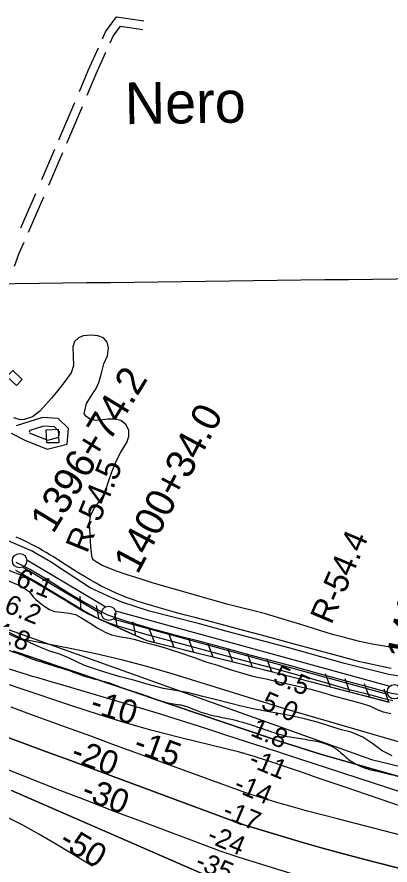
# Model space of a CAD drawing. Extents: x 3734862 to 3772949, y 391520 to 417239.
# Drawn here: x 3742804 to 3744100, y 406999 to 409950 of the extents above; entities that cross this region are included whole.
import ezdxf

# ---------------------------------------------------------------- set-up
doc = ezdxf.new("R2010")
doc.units = 0
for name, color, linetype in [('V-BLDG-OTLN', 7, 'Continuous'), ('V-FLOD-BASE', 7, 'Continuous'), ('V-GRID-MAJR', 7, 'Continuous'), ('V-LEVE-TOET', 7, 'Continuous'), ('V-RIVR-EDGE', 7, 'Continuous'), ('V-RIVR-RANG', 7, 'Continuous'), ('V-RIVR-RANG-IDEN', 7, 'Continuous'), ('V-ROAD-CNTR', 7, 'Continuous'), ('V-RRAP-FSHR', 7, 'Continuous'), ('V-SITE-VEGE', 7, 'Continuous'), ('V-SURV-IDEN', 7, 'Continuous'), ('V-SURV-LINE', 7, 'Continuous'), ('V-TOPO-DPTH', 7, 'Continuous'), ('V-TOPO-GNAM-IDEN', 7, 'Continuous'), ('V-TOPO-MAJR', 7, 'Continuous'), ('V-TOPO-MAJR-IDEN', 7, 'Continuous'), ('V-TOPO-MINR', 7, 'Continuous'), ('V-TOPO-MINR-IDEN', 7, 'Continuous'), ('V-TOPO-WATR', 7, 'Continuous')]:
    doc.layers.add(name, color=color, linetype=linetype)

msp = doc.modelspace()

# ---------------------------------------------------------------- linework, layer by layer
at = {"layer": 'V-BLDG-OTLN'}
for points in [[(3742788.9, 408720.5), (3742822, 408688.6), (3742801.7, 408667.5), (3742768.2, 408699.8)], [(3742907.2, 408468.1), (3742904.8, 408513.3), (3742946.3, 408515.6), (3742948.7, 408468.9)]]:
    msp.add_lwpolyline(points, close=True, dxfattribs=at)
at = {"layer": 'V-FLOD-BASE'}
msp.add_lwpolyline([(3742799.2, 408053.1), (3742853, 408026.1), (3742909.9, 407993.3), (3742979.3, 407948.5), (3743033, 407916.4), (3743093.5, 407882.5), (3743118.4, 407870.1), (3743180.9, 407848.5), (3743270.2, 407822.1), (3743352.5, 407800.2), (3743431.3, 407780.8), (3743537.5, 407751.6), (3743621.3, 407728.9), (3743741.1, 407696.7), (3743844, 407668.5), (3743951.5, 407639.3), (3744046.6, 407613.7), (3744099.5, 407598.1), (3744126.7, 407594.1)], dxfattribs=at)
at = {"layer": 'V-GRID-MAJR'}
msp.add_spline([(3738908.6, 408973.5), (3741556.3, 409006.9), (3746851.6, 409074.3), (3752147, 409142.5), (3757442.4, 409211.4), (3762737.7, 409281.1), (3768033.1, 409351.6), (3770680.7, 409387.1)], degree=3, dxfattribs=at)
at = {"layer": 'V-LEVE-TOET'}
for points in [[(3744215.9, 407644.2), (3744095.8, 407661.7), (3743941.3, 407700.9), (3743748.5, 407754.7), (3743534.5, 407811.6), (3743437.6, 407838.2), (3743263.6, 407883.2), (3743167.7, 407913.4), (3743132.9, 407929.5), (3743057.5, 407964.3), (3742970.5, 408021.1), (3742919.8, 408054.2), (3742853.7, 408092.6), (3742773.2, 408127.8)], [(3742798.5, 408024.9), (3742869.2, 407985.5), (3742995.7, 407909.4), (3743042.3, 407880.5), (3743097.7, 407851.4), (3743145.9, 407833.8), (3743246.4, 407803.5), (3743394.2, 407764.3), (3743526.5, 407727.8), (3743703, 407681.8), (3743863, 407637.4), (3743952.8, 407610.8), (3744015.4, 407596.7), (3744070.8, 407581.5), (3744109.3, 407572.1)]]:
    msp.add_lwpolyline(points, dxfattribs=at)
at = {"layer": 'V-RIVR-EDGE'}
msp.add_spline([(3740900.6, 408488.8), (3740941.7, 408478.3), (3740985.5, 408468.7), (3741012.2, 408464.1), (3741026.2, 408456.3), (3741048.3, 408440), (3741059.6, 408430.9), (3741079.5, 408419.1), (3741115.6, 408401), (3741134.5, 408387.8), (3741159.8, 408374.2), (3741187.8, 408359.6), (3741219.5, 408345.5), (3741247.5, 408335.1), (3741273.7, 408327.8), (3741324.3, 408308.2), (3741367.6, 408293.6), (3741397.4, 408282.7), (3741437.2, 408266.3), (3741481, 408247.7), (3741515.8, 408234), (3741546.1, 408221.7), (3741577.7, 408210.8), (3741596.2, 408209.4), (3741611.6, 408211.2), (3741627.9, 408209.8), (3741654.5, 408199.8), (3741683.9, 408190.2), (3741714.6, 408176.6), (3741739.9, 408164.7), (3741769.2, 408150.2), (3741796.8, 408143.4), (3741811.3, 408142.9), (3741833, 408141.9), (3741852, 408139.2), (3741871.9, 408137.3), (3741889, 408130.9), (3741941.9, 408104.1), (3741978.4, 408082.3), (3742006.4, 408070), (3742031.3, 408063.2), (3742056.1, 408055.9), (3742093.6, 408044.1), (3742137, 408031.3), (3742175.9, 408019), (3742202.5, 408008.5), (3742263, 407982.6), (3742313.2, 407957.1), (3742385.9, 407923.1), (3742430.1, 407901.7), (3742465.8, 407884.9), (3742513.7, 407864.4), (3742632, 407810.8), (3742679, 407791.7), (3742732.3, 407768), (3742777.5, 407745.7), (3742821.3, 407730.3), (3742862.4, 407714.3), (3742898.5, 407703.4), (3742934.7, 407691.5), (3742978.1, 407678.3), (3743028.2, 407660.1), (3743075.6, 407646), (3743127.6, 407631.8), (3743163.7, 407617.7), (3743235.1, 407594.5), (3743327.3, 407564), (3743354.9, 407558.9), (3743372.9, 407556.2), (3743388.8, 407552.5), (3743422.2, 407539.3), (3743470.5, 407523.4), (3743543.3, 407507.4), (3743582.6, 407497.8), (3743628.7, 407483.2), (3743673, 407468.2), (3743714.5, 407454.9), (3743752.5, 407444.9), (3743782.3, 407441.2), (3743812.6, 407435.3), (3743846, 407429.8), (3743877.2, 407420.6), (3743909.3, 407405.6), (3743934.1, 407386.1), (3743951.2, 407370.7), (3743984.2, 407349.4), (3744023, 407333.5), (3744066, 407323), (3744101.7, 407314.7), (3744133.8, 407306.5), (3744170.4, 407296.9), (3744207.4, 407286.9), (3744225, 407281.9), (3744312.2, 407256.8), (3744386.8, 407239.4), (3744416.2, 407234.4), (3744442.4, 407231.1), (3744469.5, 407231.5), (3744498.9, 407232.4), (3744525.6, 407231.4), (3744550, 407229.1), (3744580.7, 407220.9), (3744636.8, 407206.2), (3744682.4, 407187.6), (3744706.3, 407179.4), (3744748.4, 407171.6), (3744781.8, 407164.7), (3744803.1, 407162.9), (3744835.6, 407151), (3744852.3, 407141.5), (3744920.9, 407114.2), (3744972.9, 407087.9), (3745004.9, 407074.7), (3745034.3, 407066.9), (3745066.9, 407060), (3745090.8, 407058.2), (3745113.4, 407050.9), (3745145.9, 407034.1), (3745173, 407020.9), (3745183.4, 407002.8), (3745197.8, 406988.3), (3745221.3, 406974.6), (3745251.1, 406965.5), (3745295.8, 406956.4), (3745336.1, 406954.5), (3745373.6, 406952.6), (3745408, 406947.5), (3745450, 406939.3), (3745483, 406933.3), (3745526.4, 406935), (3745594.2, 406936.6), (3745631.8, 406936.6), (3745647.6, 406941), (3745660.7, 406948.7), (3745673.8, 406949.1), (3745691, 406946.8), (3745714.5, 406937.7), (3745744.8, 406922.3), (3745760.5, 406906.8), (3745773.2, 406890.1), (3745781.3, 406886), (3745798, 406881), (3745819.7, 406879.6), (3745874.4, 406866.3), (3745905.1, 406854.5), (3745930.8, 406838.6), (3745969.2, 406814.1), (3745999, 406799.1), (3746028.8, 406787.3), (3746069.5, 406776.8), (3746110.2, 406766.7), (3746145, 406757.1), (3746173.9, 406747.1), (3746214.5, 406737.1), (3746271.5, 406722.5), (3746336.1, 406708.3), (3746374.5, 406695.1), (3746423.3, 406678.7), (3746514.1, 406654.9), (3746563.4, 406641.3), (3746619.4, 406622.1), (3746668.6, 406606.2), (3746708.4, 406594.3), (3746774.4, 406574.3), (3746826.3, 406564.6), (3746866.1, 406562.7), (3746897.3, 406558.1), (3746931.7, 406550.4)], degree=3, dxfattribs=at)
at = {"layer": 'V-ROAD-CNTR'}
for points in [[(3743100.7, 409874.1), (3743111.7, 409898.8), (3743149.6, 409950.4), (3743244.8, 409936.4)], [(3743127.4, 409860.3), (3743137.8, 409883.7), (3743163.1, 409918.1), (3743240.5, 409906.7)], [(3743020.5, 409690.6), (3743051.5, 409764), (3743086.7, 409842.7)], [(3743047.9, 409678.3), (3743079.1, 409752), (3743112.8, 409827.7)], [(3742949.2, 409522.5), (3742966.5, 409563.1), (3743004.4, 409652.5)], [(3742976.7, 409510.7), (3742994.1, 409551.3), (3743031.3, 409639)], [(3742890.1, 409384.6), (3742935.3, 409490)], [(3742914.3, 409365.1), (3742962.8, 409478.2)], [(3742817.4, 409216.5), (3742869.2, 409335.9)], [(3742843.7, 409201.8), (3742896.7, 409323.9)], [(3742795.3, 409083.6), (3742811.7, 409128.1), (3742828.3, 409166.3)], [(3742783.6, 408502.5), (3742830.8, 408477.3), (3742908.8, 408446), (3742977.4, 408464.2), (3742982.3, 408518.8), (3742947, 408553), (3742892.4, 408556.7), (3742800.4, 408527.3)], [(3742845.7, 408503.6), (3742910.7, 408477.5), (3742949.4, 408487.8), (3742951.2, 408507.2), (3742934, 408523.8), (3742896.1, 408526.4), (3742848.6, 408511.2), (3742846.1, 408505.2)], [(3744104.1, 407683.3), (3744082.2, 407687.5), (3744060.4, 407691.9), (3744038.6, 407696.6), (3744016.8, 407701.5), (3743995.1, 407706.6), (3743918.1, 407727.7), (3743841, 407748.4), (3743763.8, 407768.8), (3743670.8, 407793.9), (3743577.7, 407819), (3743484.7, 407844), (3743452.9, 407852), (3743421.1, 407860.3), (3743389.4, 407868.7), (3743357.7, 407877.3), (3743326.1, 407886.2), (3743294.6, 407895.3), (3743263.1, 407904.6), (3743249.8, 407908.4), (3743236.7, 407912.5), (3743223.5, 407916.8), (3743210.5, 407921.2), (3743197.5, 407925.9), (3743184.6, 407930.7), (3743171.7, 407935.8), (3743159, 407941), (3743146.3, 407946.4), (3743133.7, 407952.1), (3743121.2, 407957.9), (3743108.8, 407963.9), (3743096.5, 407970.1), (3743076.8, 407981), (3743057.4, 407992.2), (3743038, 408003.5), (3743018.7, 408015.1), (3742999.5, 408026.8), (3742980.5, 408038.8), (3742961.6, 408050.9), (3742942.8, 408063.2), (3742930.5, 408071.2), (3742918, 408079), (3742905.4, 408086.7), (3742892.7, 408094.1), (3742879.9, 408101.3), (3742867, 408108.3), (3742854, 408115.2), (3742840.8, 408121.8), (3742827.6, 408128.2), (3742814.3, 408134.4), (3742800.9, 408140.4)]]:
    msp.add_lwpolyline(points, dxfattribs=at)
at = {"layer": 'V-RRAP-FSHR'}
for p, q in [((3743026.8, 407886.4), (3743023.4, 407935.1)), ((3743089.2, 407854.8), (3743080.2, 407902.8)), ((3743153, 407826), (3743143.9, 407874)), ((3743216.7, 407797.1), (3743207.7, 407845.1)), ((3743282.1, 407772.9), (3743264.6, 407818.5)), ((3743350.1, 407756.1), (3743332.5, 407801.6)), ((3743418, 407739.2), (3743400.5, 407784.8)), ((3743485.9, 407722.3), (3743468.4, 407767.9)), ((3743553.9, 407705.4), (3743536.3, 407751)), ((3743621.7, 407688.3), (3743604.5, 407734)), ((3743689.6, 407671), (3743672.3, 407716.7)), ((3743892.9, 407618.7), (3743875.9, 407664.4)), ((3743960.7, 407601.1), (3743943.6, 407646.8)), ((3744028.4, 407583.5), (3744011.4, 407629.2)), ((3744096.2, 407565.8), (3744079.1, 407611.6))]:
    msp.add_line(p, q, dxfattribs=at)
for points in [[(3744098.3, 407565.3), (3743827.4, 407635.7), (3743592.3, 407695.9), (3743255.4, 407779.6), (3743049.2, 407873), (3742833, 408002.6), (3742229.9, 408229.5), (3742052.9, 408246.4), (3741887.5, 408295.6), (3741885.3, 408291.4)], [(3742367.7, 407964), (3744035.9, 407366.8), (3745769.8, 406946.2), (3746228.8, 406810.1), (3747274.2, 406525.6), (3748829.6, 406241.1), (3749734.8, 405944.3), (3750537.9, 405672.1), (3750818.4, 405622.6)], [(3743026.8, 407886.4), (3742980.5, 407914.1)], [(3743089.2, 407854.8), (3743049.2, 407873), (3743026.8, 407886.4)], [(3743153, 407826), (3743089.2, 407854.8)], [(3743216.7, 407797.1), (3743153, 407826)], [(3743282.1, 407772.9), (3743255.4, 407779.6), (3743216.7, 407797.1)], [(3743350.1, 407756.1), (3743282.1, 407772.9)], [(3743418, 407739.2), (3743350.1, 407756.1)], [(3743485.9, 407722.3), (3743418, 407739.2)], [(3743553.9, 407705.4), (3743485.9, 407722.3)], [(3743621.7, 407688.3), (3743592.3, 407695.9), (3743553.9, 407705.4)], [(3743689.6, 407671), (3743621.7, 407688.3)], [(3743693.5, 407670), (3743689.6, 407671)], [(3743892.9, 407618.7), (3743878.8, 407622.4)], [(3743960.7, 407601.1), (3743892.9, 407618.7)], [(3744028.4, 407583.5), (3743960.7, 407601.1)], [(3744096.2, 407565.8), (3744028.4, 407583.5)]]:
    msp.add_lwpolyline(points, dxfattribs=at)
at = {"layer": 'V-SITE-VEGE'}
for points in [[(3743085.1, 408840.3), (3743061.6, 408842.5), (3743034.1, 408841.1), (3743017.5, 408834.3), (3743003.1, 408820.6), (3742997.7, 408802.8), (3742999.6, 408737.5), (3742992.3, 408711.9), (3742969.3, 408682), (3742946, 408650.8), (3742923.4, 408623.4), (3742903, 408600.7), (3742882.6, 408578.2), (3742857.1, 408558.6), (3742829, 408549.1), (3742815.2, 408548.8), (3742792.1, 408555.5)], [(3744135.4, 407751.9), (3744092.9, 407758), (3744037.9, 407767.3), (3743993.8, 407776.6), (3743942.3, 407791.2), (3743899.5, 407801.7), (3743789.6, 407836), (3743724.1, 407856), (3743667.3, 407873.7), (3743621.7, 407885.2), (3743578.6, 407895.4), (3743537.6, 407905.6), (3743484.3, 407920.8), (3743435.5, 407934.8), (3743383.1, 407949.4), (3743325, 407966.3), (3743270.1, 407982.8), (3743228.2, 407996.1), (3743187, 408009.1), (3743149.6, 408021.8), (3743099.3, 408041.1), (3743070, 408060), (3743064.4, 408068.4), (3743061.4, 408095), (3743059, 408122.8), (3743057.6, 408150.1), (3743055.2, 408184.8), (3743059.1, 408213.8), (3743070.2, 408238.8), (3743087.8, 408262.2), (3743103.8, 408285.2), (3743113.9, 408308), (3743121.3, 408333.3), (3743132.6, 408363.6), (3743148.8, 408404.5), (3743163.6, 408433.2), (3743186, 408471.8), (3743192, 408491.5), (3743192.7, 408511.2), (3743183.1, 408530.9), (3743164.7, 408545.7), (3743146, 408550.2), (3743119.1, 408551.2), (3743102.2, 408548.2), (3743077.2, 408545.8), (3743059.4, 408549.3), (3743043.2, 408561.3), (3743037.3, 408570), (3743038.9, 408580.3), (3743045.3, 408605.6), (3743067.3, 408640.2), (3743079.3, 408657.1), (3743087.5, 408678.9), (3743097.6, 408710.5), (3743105.6, 408742.9), (3743117.9, 408771.3), (3743121.8, 408799.4), (3743117.5, 408818.9), (3743104.7, 408833.9), (3743085.1, 408840.3)], [(3742710.7, 408015.2), (3742817.7, 407969.5), (3742845.5, 407950.5), (3742858.1, 407934.1), (3742869, 407923.6), (3742881.3, 407913), (3742896.9, 407901.1), (3742916.4, 407888.9), (3742934.1, 407881.9), (3742956.7, 407879.1), (3742985.1, 407875.9), (3743006.7, 407870.8), (3743025, 407860.6), (3743058.1, 407840.7), (3743084.4, 407823), (3743109.5, 407809.2), (3743132.6, 407800.2), (3743153.9, 407795.4), (3743171.4, 407792.7), (3743194.5, 407788.8), (3743214.3, 407784.2), (3743240.6, 407776.1), (3743281.4, 407765.5), (3743314.7, 407756.7), (3743346.8, 407746.3), (3743368.3, 407738.7), (3743423.1, 407720.1), (3743459.8, 407706), (3743500.7, 407694.4), (3743541.1, 407680.7), (3743567, 407672.7), (3743595.2, 407664.3), (3743618, 407657.7), (3743643.8, 407652.2), (3743669.8, 407646.9), (3743697.4, 407639.8), (3743774.6, 407623), (3743824.5, 407610.8), (3743865, 407599.5), (3743911.4, 407586.1), (3743964.7, 407571.3), (3744003.5, 407561.4), (3744031.6, 407551.7), (3744054.7, 407540.5), (3744075.8, 407532), (3744102.2, 407526.9)], [(3744107.8, 407379.4), (3744072.6, 407397.1), (3744040, 407420.7), (3744004.9, 407444.5), (3743964.9, 407461.5), (3743926.7, 407470.5), (3743851.5, 407495.2), (3743803.1, 407507.9), (3743760.9, 407517.7), (3743719.8, 407525.3), (3743673.3, 407533.5), (3743624, 407542.6), (3743582.4, 407552), (3743546.7, 407560.8), (3743491.9, 407575.3), (3743449.7, 407586.1), (3743395.6, 407599.2), (3743313.2, 407614.1), (3743259.6, 407627.7), (3743212.6, 407641.3), (3743162, 407654.4), (3743127.1, 407664.8), (3743087, 407677.1), (3743038, 407693.9), (3742982.7, 407720), (3742948.7, 407733.7), (3742919.8, 407742.8), (3742886, 407755.7), (3742851.7, 407771.4), (3742774, 407809.5)]]:
    msp.add_lwpolyline(points, dxfattribs=at)
at = {"layer": 'V-SURV-LINE'}
for points in [[(3742837.5, 408061.2), (3743112.7, 407898)], [(3743097.4, 407872.2), (3742822.2, 408035.3)], [(3743145.5, 407884.1), (3744099.8, 407622)], [(3744091.9, 407593), (3743137.5, 407855.2)]]:
    msp.add_lwpolyline(points, dxfattribs=at)
for centre in [(3742812.7, 408058.4), (3743122.2, 407875), (3744115.1, 407602.2)]:
    msp.add_circle(centre, 25, dxfattribs=at)
at = {"layer": 'V-TOPO-DPTH'}
for points in [[(3742791.6, 407743.8), (3742813.9, 407736), (3742836.4, 407728.3), (3742952, 407689.1), (3743032.2, 407661.9), (3743112.4, 407634.7), (3743192.7, 407607.5), (3743272.9, 407580.3), (3743684.8, 407440.4), (3743691.4, 407438.2), (3743697.9, 407436), (3743704.5, 407433.9), (3743711, 407431.8), (3743777.9, 407410.2), (3743818, 407397.5), (3743858.2, 407385.1), (3743898.5, 407373.1), (3743938.9, 407361.4), (3744522.4, 407196)], [(3744491.9, 407082.1), (3743937.1, 407272.4), (3743892.2, 407287.8), (3743847.3, 407303.1), (3743802.4, 407318.4), (3743757.4, 407333.7), (3743675.2, 407361.5), (3743671.4, 407362.8), (3743667.5, 407364.1), (3743663.6, 407365.4), (3743659.7, 407366.7), (3743641.9, 407372.5), (3743629, 407376.6), (3743616.1, 407380.6), (3743603.2, 407384.3), (3743590.2, 407388), (3743587.3, 407388.8), (3743572.8, 407392.7), (3743558.3, 407396.5), (3743543.8, 407400.3), (3743529.3, 407403.9), (3743368.5, 407443.2), (3743273.9, 407467.7), (3743179.8, 407493.9), (3743086.5, 407522.5), (3742993.6, 407552.9), (3742807.6, 407616.3), (3742777.9, 407626.5)], [(3744491.9, 407082.1), (3743937.1, 407272.4), (3743892.2, 407287.8), (3743847.3, 407303.1), (3743802.4, 407318.4), (3743757.4, 407333.7), (3743675.2, 407361.5), (3743671.4, 407362.8), (3743667.5, 407364.1), (3743663.6, 407365.4), (3743659.7, 407366.7), (3743641.9, 407372.5), (3743629, 407376.6), (3743616.1, 407380.6), (3743603.2, 407384.3), (3743590.2, 407388), (3743587.3, 407388.8), (3743572.8, 407392.7), (3743558.3, 407396.5), (3743543.8, 407400.3), (3743529.3, 407403.9), (3743368.5, 407443.2), (3743273.9, 407467.7), (3743179.8, 407493.9), (3743086.5, 407522.5), (3742993.6, 407552.9), (3742807.6, 407616.3), (3742777.9, 407626.5)], [(3742742.6, 407453.6), (3742831.7, 407420.9), (3742906, 407393.6), (3742980.3, 407366.2), (3743054.5, 407338.6), (3743128.7, 407311), (3743546.2, 407155.3), (3743560.4, 407150.2), (3743574.6, 407145.2), (3743588.9, 407140.5), (3743603.2, 407136), (3743719.7, 407100.6), (3743792.5, 407079), (3743865.5, 407058), (3743938.7, 407038), (3744012.1, 407018.6), (3744442.9, 406907.7)], [(3742742.6, 407453.6), (3742831.7, 407420.9), (3742906, 407393.6), (3742980.3, 407366.2), (3743054.5, 407338.6), (3743128.7, 407311), (3743546.2, 407155.3), (3743560.4, 407150.2), (3743574.6, 407145.2), (3743588.9, 407140.5), (3743603.2, 407136), (3743719.7, 407100.6), (3743792.5, 407079), (3743865.5, 407058), (3743938.7, 407038), (3744012.1, 407018.6), (3744442.9, 406907.7)], [(3743774, 406964), (3743572.2, 407026.8), (3743551.3, 407033.5), (3743530.4, 407040.5), (3743509.7, 407047.8), (3743489.1, 407055.3), (3743245.8, 407146.7), (3743145.3, 407184.8), (3743044.9, 407223.3), (3742944.8, 407262.4), (3742844.8, 407301.9), (3742702.7, 407358.5)], [(3743774, 406964), (3743572.2, 407026.8), (3743551.3, 407033.5), (3743530.4, 407040.5), (3743509.7, 407047.8), (3743489.1, 407055.3), (3743245.8, 407146.7), (3743145.3, 407184.8), (3743044.9, 407223.3), (3742944.8, 407262.4), (3742844.8, 407301.9), (3742702.7, 407358.5)], [(3742784.9, 407259), (3743453.6, 406966.4)], [(3742784.9, 407259), (3743453.6, 406966.4)]]:
    msp.add_lwpolyline(points, dxfattribs=at)
at = {"layer": 'V-TOPO-MAJR'}
msp.add_lwpolyline([(3743066, 406995.2), (3742935.3, 407073.8), (3742879.6, 407106.2), (3742823.4, 407137.5), (3742766.3, 407167.2)], dxfattribs=at)
at = {"layer": 'V-TOPO-MINR'}
for points in [[(3744611.2, 407287.5), (3743742.3, 407540.8), (3743342.8, 407664.3), (3743255.1, 407689.8), (3743167, 407713.4), (3743078.1, 407734.1), (3742988.7, 407752.9), (3742809.2, 407787.5), (3742137.6, 408094.3)], [(3744195.1, 407233.7), (3743729.4, 407386.2), (3743706.3, 407393.8), (3743683.2, 407401.4), (3743660.2, 407408.9), (3743637.1, 407416.5), (3743529.5, 407451.7), (3743452.6, 407476.5), (3743375.5, 407501), (3743298.3, 407524.8), (3743220.9, 407548.2), (3742974.1, 407621.7), (3742951.7, 407628.4), (3742929.3, 407634.9), (3742906.9, 407641.4), (3742884.5, 407647.8), (3742876, 407650.2), (3742857.8, 407655.5), (3742839.7, 407661), (3742821.6, 407666.7), (3742803.6, 407672.6), (3742778.1, 407681)], [(3744491.9, 407082.1), (3743937.1, 407272.4), (3743892.2, 407287.8), (3743847.3, 407303.1), (3743802.4, 407318.4), (3743757.4, 407333.7), (3743675.2, 407361.5), (3743671.4, 407362.8), (3743667.5, 407364.1), (3743663.6, 407365.4), (3743659.7, 407366.7), (3743641.9, 407372.5), (3743629, 407376.6), (3743616.1, 407380.6), (3743603.2, 407384.3), (3743590.2, 407388), (3743587.3, 407388.8), (3743572.8, 407392.7), (3743558.3, 407396.5), (3743543.8, 407400.3), (3743529.3, 407403.9), (3743368.5, 407443.2), (3743273.9, 407467.7), (3743179.8, 407493.9), (3743086.5, 407522.5), (3742993.6, 407552.9), (3742807.6, 407616.3), (3742777.9, 407626.5)], [(3744498.5, 407009.5), (3743912.3, 407160.8), (3743862.8, 407173.8), (3743813.4, 407187.1), (3743764, 407200.9), (3743714.8, 407215), (3743638.2, 407237.4), (3743627.4, 407240.7), (3743616.6, 407244.1), (3743605.9, 407247.7), (3743595.2, 407251.5), (3743127.8, 407422.4), (3743060.1, 407447.1), (3742992.4, 407471.9), (3742924.7, 407496.6), (3742857, 407521.2), (3742783.6, 407548)], [(3744442.9, 406907.7), (3744012.1, 407018.6), (3743938.7, 407038), (3743865.5, 407058), (3743792.5, 407079), (3743719.7, 407100.6), (3743603.2, 407136), (3743588.9, 407140.5), (3743574.6, 407145.2), (3743560.4, 407150.2), (3743546.2, 407155.3), (3743128.7, 407311), (3743054.5, 407338.6), (3742980.3, 407366.2), (3742906, 407393.6), (3742831.7, 407420.9), (3742742.6, 407453.6)], [(3743774, 406964), (3743572.2, 407026.8), (3743551.3, 407033.5), (3743530.4, 407040.5), (3743509.7, 407047.8), (3743489.1, 407055.3), (3743245.8, 407146.7), (3743145.3, 407184.8), (3743044.9, 407223.3), (3742944.8, 407262.4), (3742844.8, 407301.9), (3742702.7, 407358.5)], [(3743453.6, 406966.4), (3742784.9, 407259)]]:
    msp.add_lwpolyline(points, dxfattribs=at)
at = {"layer": 'V-TOPO-WATR'}
msp.add_lwpolyline([(3744522.4, 407196), (3743938.9, 407361.4), (3743898.5, 407373.1), (3743858.2, 407385.1), (3743818, 407397.5), (3743777.9, 407410.2), (3743711, 407431.8), (3743704.5, 407433.9), (3743697.9, 407436), (3743691.4, 407438.2), (3743684.8, 407440.4), (3743272.9, 407580.3), (3743192.7, 407607.5), (3743112.4, 407634.7), (3743032.2, 407661.9), (3742952, 407689.1), (3742836.4, 407728.3), (3742813.9, 407736), (3742791.6, 407743.8)], dxfattribs=at)

# ---------------------------------------------------------------- texts
at = {"layer": 'V-RIVR-RANG'}
for s, rotation, p in [('6.1', 337.8383, (3742794.7, 407973.2)), ('6.2', 337.8383, (3742755, 407881.4)), ('4.8', 337.8383, (3742717.5, 407788.7)), ('5.5', 336.9183, (3743689.5, 407635.6)), ('5.0', 336.9183, (3743647.8, 407544.6)), ('1.8', 336.9183, (3743611.5, 407451.4)), ('-11', 337.2006, (3743604.6, 407345.4)), ('-14', 337.2006, (3743553, 407258.6)), ('-17', 337.2006, (3743513.5, 407166.7)), ('-24', 337.2006, (3743459.5, 407081)), ('-35', 337.2006, (3743418.3, 406989.8))]:
    msp.add_text(s, height=67, rotation=rotation, dxfattribs=at).set_placement(p)
at = {"layer": 'V-RIVR-RANG-IDEN'}
for s, rotation, p in [('R-54.5', 67.9801, (3743046.7, 408080.8)), ('R-54.4', 67.0589, (3743896, 407833))]:
    msp.add_text(s, height=83, rotation=rotation, dxfattribs=at).set_placement(p)
at = {"layer": 'V-SURV-IDEN'}
for s, rotation, p in [('1396+74.2', 58.6144, (3742929.2, 408148.9)), ('1400+34.0', 61.8878, (3743222.6, 408007.5)), ('1410+63.8', 78.4339, (3744185.2, 407708))]:
    msp.add_text(s, height=100, rotation=rotation, dxfattribs=at).set_placement(p)
at = {"layer": 'V-TOPO-GNAM-IDEN'}
msp.add_text('Nero', height=145, rotation=0.8376, dxfattribs=at).set_placement((3743179.2, 409577))
at = {"layer": 'V-TOPO-MAJR-IDEN'}
msp.add_text('-50', height=83, rotation=328.9869, dxfattribs=at).set_placement((3742944.4, 407068.4))
at = {"layer": 'V-TOPO-MINR-IDEN'}
for s, rotation, p in [('-10', 342.9387, (3743053.3, 407532.7)), ('-15', 339.9138, (3743203.9, 407394.6)), ('-20', 339.5918, (3742986.1, 407364.1)), ('-30', 339.0138, (3743022.7, 407231.8))]:
    msp.add_text(s, height=83, rotation=rotation, dxfattribs=at).set_placement(p)

doc.saveas('drawing.dxf')
